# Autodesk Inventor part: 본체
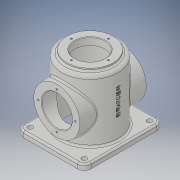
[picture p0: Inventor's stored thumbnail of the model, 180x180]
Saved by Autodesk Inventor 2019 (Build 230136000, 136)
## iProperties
Created: 2020-12
Part Number: 본체
Material: 일반
Document SubType Name: Modeling
Designer: jun-1-6
Density: 1 g/cm^3
Appearance: 기본값
Mass: 457.576 g
Surface Area: 1067.12 cm^2
Volume: 457.576 cm^3
Author: jun-1-6
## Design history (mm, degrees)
sketch "스케치1"
  geometry: C1 r 50 at (0, 0); 1 further point
  constraints: 1 centre point, 1 coincident
  dimensions: "d0" = 100 diameter of C1
extrude "돌출1" new body sketch "스케치1" distance "d1" = 60; taper "d3" = 0 deg; dims "d2" = 50, "d4" = 0
sketch "스케치2"
  geometry: C1 r 41 at (0, 0); 1 further point
  constraints: 1 centre point, 1 coincident
  dimensions: "d5" = 82 diameter of C1
extrude "돌출2" join sketch "스케치2" distance "d6" = 5; taper "d7" = 0 deg
sketch "스케치3"
  geometry: L1 (60, 70)-(-60, 70); L2 (-60, 70)-(-60, -70); L3 (-60, -70)-(60, -70); L4 (60, -70)-(60, 70); L5 (60, 70)-(-60, -70); L6 (-60, 70)-(60, -70); 1 further point
  constraints: 12 end point, 2 midpoint, 2 parallel, 1 horizontal, 1 perpendicular
  dimensions: "d8" = 120 distance of L3.end L2.end; "d9" = 140 distance of L2.end L1.end
extrude "돌출3" join sketch "스케치3" distance "d10" = 10; taper "d11" = 0 deg
fillet "모깎기1" dims "d12" = 12
sketch "스케치4"
  geometry: A1 r 12 centre (-48, -58) between (-60, -58) and (-48, -70) reference; 2 further points
  constraints: 1 coincident
hole "구멍1" sketch "스케치4" at (-48, -58) diameter "d13" = 9; stored, may be unused: countersink angle "d17" = 90 deg, drill point angle "d19" = 118 deg; dims "d14" = 18, "d15" = 4, "d16" = 2, "d18" = 22
sketch "스케치5"
  geometry: C1 r 42 at (0, 0); 1 further point
  constraints: 1 centre point, 1 coincident
  dimensions: "d20" = 84 diameter of C1
extrude "돌출4" cut sketch "스케치5" distance "d21" = 112; taper "d22" = 0 deg
sketch "스케치6"
  geometry: C1 r 41 at (0, 0) reference; 2 further points
  constraints: 1 coincident
hole "구멍2" sketch "스케치6" at (0, 0) diameter "d23" = 54; stored, may be unused: countersink angle "d27" = 90 deg, drill point angle "d29" = 118 deg; dims "d24" = 18, "d25" = 4, "d26" = 2, "d28" = 22
node "작업 평면1"
sketch "스케치7"
  geometry: C1 r 41 at (0, 0); 1 further point
  constraints: 1 centre point, 1 coincident
  dimensions: "d31" = 82 diameter of C1
extrude "돌출5" join sketch "스케치7" stored distance "d32" = 112; taper "d33" = 0 deg
sketch "스케치8"
  geometry: C1 r 41 at (0, 0) reference; 2 further points
  constraints: 1 coincident
hole "구멍3" sketch "스케치8" at (0, 0) diameter "d34" = 54; stored, may be unused: countersink angle "d38" = 90 deg, drill point angle "d40" = 118 deg; dims "d35" = 18, "d36" = 4, "d37" = 2, "d39" = 22
fillet "모깎기2" dims "d41" = 3
fillet "모깎기3" dims "d42" = 3
fillet "모깎기4" dims "d43" = 3
fillet "모깎기5" dims "d44" = 6
chamfer "모따기1" distance "d45" = 1; stored, may be unused: second distance "d46" = 2, angle "d47" = 45 deg
fillet "모깎기6" dims "d48" = 3
node "작업 평면2"
sketch "스케치9"
  geometry: L1 (-60, -42)-(-60, 42) reference; 2 further points
  constraints: 1 horizontal alignment, 1 other
  dimensions: "d49" = 70 distance from line of L1 point (10, 0)
feature "엠보싱1" sketch "스케치9" dims "d1" = 60, "d12" = 12, "d50" = 0.5, "d51" = 0
fillet "모깎기7" dims "d52" = 3
sketch "스케치10"
  geometry: 2 further points
  constraints: 1 vertical alignment
  dimensions: "d53" = 33 distance of point (0, 0) point (0, 33)
hole "구멍4" sketch "스케치10" at (0, 33) diameter "d54" = 3.242; stored, may be unused: countersink angle "d58" = 90 deg, drill point angle "d60" = 118 deg; dims "d55" = 8, "d56" = 4, "d57" = 2, "d59" = 10
sketch "스케치11"
  geometry: 2 further points
  constraints: 1 vertical alignment
  dimensions: "d64" = 33 distance of point (0, 0) point (0, 33)
hole "구멍5" sketch "스케치11" at (0, 33) diameter "d65" = 3.242; stored, may be unused: countersink angle "d69" = 90 deg, drill point angle "d71" = 118 deg; dims "d66" = 8, "d67" = 4, "d68" = 2, "d70" = 10
node "솔리드1"
mirror "미러1"
mirror "미러2"
mirror "미러3"
pattern_circular "원형 패턴1" dims angle "d62" = 360 deg
mirror "미러4"
pattern_circular "원형 패턴2" dims angle "d73" = 360 deg
other parameters: "d30" = 59
